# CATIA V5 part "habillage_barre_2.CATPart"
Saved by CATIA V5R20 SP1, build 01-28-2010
Part number: habillage_barre_2
Bounding box of the stored display mesh (mm): x 20 to 40, y -822.801 to -679.996, z -219.993 to 272.457
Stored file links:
  C:\Users\patrice\Desktop\IFMa\Semestre 3\IAO\projet iao\iao\habillage_barre_2.CATPart
  C:\Users\patrice\Desktop\IFMa\Semestre 3\IAO\projet iao\iao\pcabanel.CATProduct
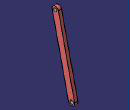
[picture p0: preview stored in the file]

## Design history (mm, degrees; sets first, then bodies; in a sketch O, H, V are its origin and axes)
External parameters (linked from other documents)
  External.AC = 200 mm
Set1
  Plane1: linked copy from another document
  Point1 "E": linked copy from another document
  Point2 "D": linked copy from another document
Body1 (main body)
  Sketch1 on Plane1, origin (0, 0, 0), H (0, 1, 0), V (0, 0, 1)
    construction line L1 (-802.8082, 252.4645) -> (-699.9886, -200)
    point P1 (-802.8082, 252.4645)
    point P2 (-699.9886, -200)
    line L2 (-783.3054, 256.8964) -> (-680.4858, -195.5681)
    line L3 (-719.4914, -204.4319) -> (-822.311, 248.0326)
    arc A1 centre (-699.9886, -200) radius 20 from (-680.4858, -195.5681) to (-719.4914, -204.4319) cw
    arc A2 centre (-802.8082, 252.4645) radius 20 from (-822.311, 248.0326) to (-783.3054, 256.8964) cw
    reference projected point E1 (-699.9886, -200) from Point1
    reference projected point E2 (-802.8082, 252.4645) from Point2
    distance L1 L2 = 20 {= External.AC /10}
    tangency: A1 L2, A2 L2, A1 L3, A2 L3
    coincidence: P2 E1, P1 E2
  Pad1: profile Sketch1, direction (1, 0, 0), length 40 {= External.AC /5}, opposite side length -20 {= -External.AC /10}
  Sketch2 on end face of Pad1, origin (40, -401.4041, 126.2323), H (0, 1, 0), V (0, 0, 1)
    point P1 (-401.4041, 126.2323)
    reference projected point E1 (-401.4041, 126.2323) from Point2
    coincidence: E1 P1
  Hole1: placed by Sketch2, at (40, -802.8082, 252.4645) direction (-1, 0, 0), diameter 20 {= External.AC /10}, through (limit type 6)
  Sketch3 on end face of Pad1, origin (40, -349.9943, -100), H (0, 1, 0), V (0, 0, 1)
    point P1 (-349.9943, -100)
    reference projected point E1 (-349.9943, -100) from Point1
    coincidence: E1 P1
  Hole2: placed by Sketch3, at (40, -699.9886, -200) direction (-1, 0, 0), diameter 20 {= External.AC /10}, through (limit type 6)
